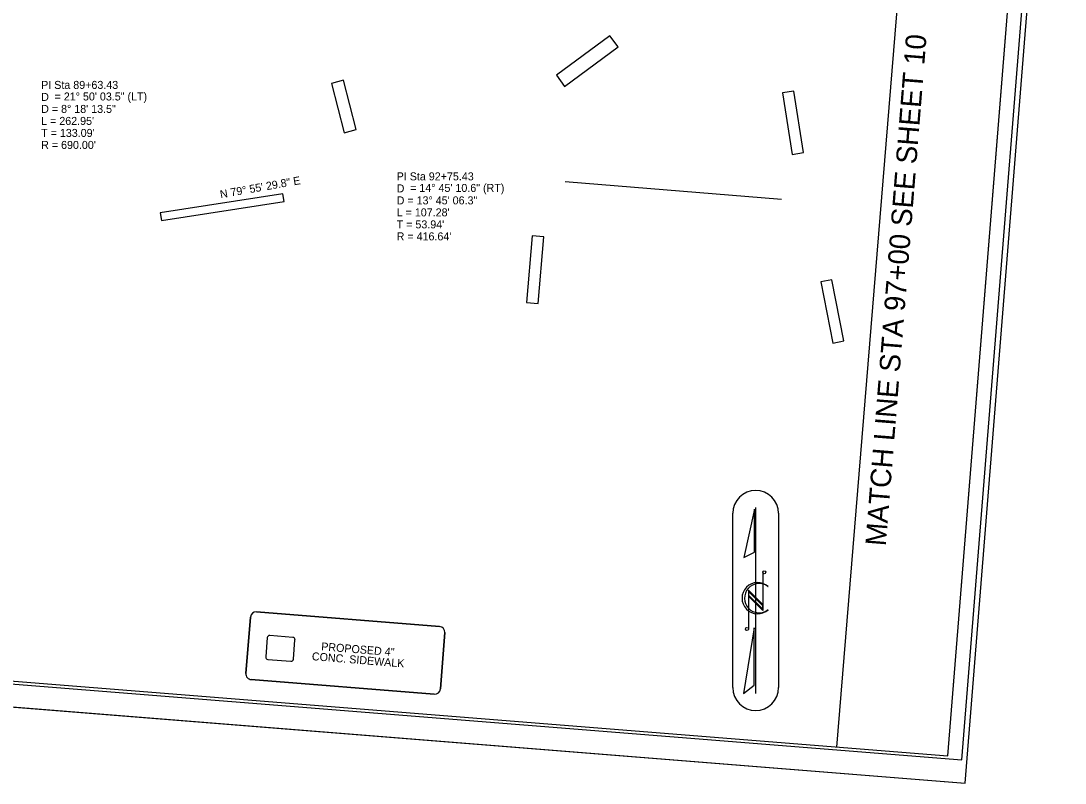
# Model space of a CAD drawing. Extents: x 928111 to 937215, y 683930 to 686530.
# Drawn here: x 935149 to 936063, y 683930 to 684597 of the extents above; entities that cross this region are included whole.
import ezdxf

# ---------------------------------------------------------------- set-up
doc = ezdxf.new("R2010")
doc.units = 0
for name, color, linetype in [('Exist Horizontal Alignment Curve and Spiral Data', 7, 'Continuous'), ('Exist Horizontal Alignment Direction Label', 7, 'Continuous'), ('Exist Horizontal Alignment Station Label', 7, 'Continuous'), ('Matchline', 7, 'Continuous'), ('Matchline Text', 7, 'Continuous'), ('Old_Level_2', 7, 'Continuous'), ('Prop DSN Text', 7, 'Continuous'), ('Prop Lane Lines', 7, 'Continuous'), ('Sheet Cutting Line CELL', 7, 'Continuous'), ('Sheet Layout Plan Border', 7, 'Continuous'), ('Sheet Plan CELL', 7, 'Continuous'), ('Sheet Plan Layout CELL', 7, 'Continuous'), ('Sheet Plot Border Inside CELL', 7, 'Continuous'), ('Sheet Plot Border Outside CELL', 7, 'Continuous')]:
    doc.layers.add(name, color=color, linetype=linetype)

msp = doc.modelspace()

# ---------------------------------------------------------------- linework, layer by layer
at = {"layer": 'Exist Horizontal Alignment Station Label'}
for p, q in [((935772.05, 684013.28), (935772.05, 684165.78)), ((935812.05, 684165.78), (935812.05, 684013.28))]:
    msp.add_line(p, q, dxfattribs=at)
for centre, start, end in [((935792.05, 684165.78), 90, 180), ((935792.05, 684165.78), 0, 90), ((935792.05, 684013.28), 180, 270), ((935792.05, 684013.28), 270, 0)]:
    msp.add_arc(centre, 20, start, end, dxfattribs=at)
at = {"layer": 'Matchline'}
msp.add_line((935863.04, 683961.34), (935931.43, 684797.06), dxfattribs=at)
at = {"layer": 'Old_Level_2'}
for p, q in [((935364.76, 684057.07), (935363.41, 684040.09)), ((935387.23, 684057.28), (935366.92, 684058.9)), ((935387.7, 684038.15), (935389.06, 684055.13)), ((935365.24, 684037.94), (935385.55, 684036.32))]:
    msp.add_line(p, q, dxfattribs=at)
for centre, start, end in [((935366.76, 684056.91), 85.42675, 175.42675), ((935387.07, 684055.29), 355.42675, 85.42675), ((935365.4, 684039.93), 175.42675, 265.42675), ((935385.71, 684038.31), 265.42675, 355.42675)]:
    msp.add_arc(centre, 2, start, end, dxfattribs=at)
at = {"layer": 'Prop DSN Text'}
for p, q in [((935350.07, 684075.01), (935346.13, 684025.71)), ((935346.13, 684025.71), (935350.07, 684075.01)), ((935515.57, 684066.79), (935355.46, 684079.6)), ((935355.46, 684079.6), (935515.57, 684066.79)), ((935516.21, 684012.1), (935520.16, 684061.41)), ((935520.16, 684061.41), (935516.21, 684012.1)), ((935350.71, 684020.33), (935510.83, 684007.52)), ((935510.83, 684007.52), (935350.71, 684020.33))]:
    msp.add_line(p, q, dxfattribs=at)
for points in [[(935624.91, 684539.21), (935671.82, 684573.75), (935664.61, 684583.55), (935617.69, 684549.01)], [(935442.67, 684501.37), (935431.47, 684544.51), (935421, 684541.79), (935432.21, 684498.66)], [(935833.97, 684481.26), (935825.5, 684535.08), (935815.37, 684533.49), (935823.84, 684479.66)], [(935272.15, 684421.83), (935379.47, 684438.5), (935378.41, 684445.34), (935271.09, 684428.67)], [(935596.62, 684408.37), (935591.66, 684350.07), (935601.84, 684349.2), (935606.81, 684407.5)], [(935848.92, 684368.17), (935859.5, 684314.68), (935869.26, 684316.61), (935858.68, 684370.1)]]:
    msp.add_lwpolyline(points, close=True, dxfattribs=at)
for centre, start, end in [((935355.06, 684074.61), 85.42675, 175.42675), ((935355.06, 684074.61), 85.42675, 175.42675), ((935515.17, 684061.81), 355.42675, 85.42675), ((935515.17, 684061.81), 355.42675, 85.42675), ((935351.11, 684025.31), 175.42675, 265.42675), ((935351.11, 684025.31), 175.42675, 265.42675), ((935511.23, 684012.5), 265.42675, 355.42675), ((935511.23, 684012.5), 265.42675, 355.42675)]:
    msp.add_arc(centre, 5, start, end, dxfattribs=at)
at = {"layer": 'Prop Lane Lines'}
msp.add_line((935625.51, 684456.02), (935814.55, 684440.55), dxfattribs=at)
at = {"layer": 'Sheet Cutting Line CELL'}
msp.add_line((934297.29, 684064), (935975.43, 683929.77), dxfattribs=at)
at = {"layer": 'Sheet Layout Plan Border'}
msp.add_line((935863.04, 683961.34), (935931.43, 684797.06), dxfattribs=at)
at = {"layer": 'Sheet Plan CELL'}
for p, q in [((935792.05, 684008.28), (935792.05, 684170.78)), ((935798.18, 684114.23), (935798.18, 684080.88)), ((935802.78, 684101.8), (935802.95, 684101.68)), ((935798.18, 684086.08), (935785.75, 684098.5)), ((935785.75, 684098.5), (935785.75, 684064.6)), ((935798.18, 684084.85), (935785.75, 684097.28)), ((935785.75, 684097.28), (935785.75, 684094.23)), ((935798.18, 684081.8), (935785.75, 684094.23)), ((935785.75, 684094.23), (935798.18, 684081.8)), ((935798.18, 684080.88), (935785.75, 684093.3)), ((935798.18, 684081.8), (935798.18, 684084.85))]:
    msp.add_line(p, q, dxfattribs=at)
for points in [[(936044.02, 685000.22), (934548.76, 685119.82), (934465.04, 684073.17), (935960.28, 683953.56)], [(935790.93, 684169.35), (935781.65, 684127.15), (935790.93, 684131.85)], [(935790.73, 684065.53), (935781.53, 684008.28), (935790.73, 684015.53)]]:
    msp.add_lwpolyline(points, close=True, dxfattribs=at)
for centre in [(935799.5, 684114.2), (935784.43, 684064.55)]:
    msp.add_circle(centre, 1.32, dxfattribs=at)
for centre, radius, start, end in [((935793.78, 684091.56), 13.65, 47.84002, 312.39406), ((935795.1, 684091.56), 12.8, 53.09504, 308.62871)]:
    msp.add_arc(centre, radius, start, end, dxfattribs=at)
at = {"layer": 'Sheet Plan Layout CELL'}
msp.add_lwpolyline([(934548.73, 685119.8), (934465.04, 684073.17), (935960.27, 683953.57), (936027.12, 684789.41), (935788.64, 684808.48), (935805.5, 685019.3)], close=True, dxfattribs=at)
at = {"layer": 'Sheet Plot Border Inside CELL'}
msp.add_lwpolyline([(934311.84, 684082.9), (935972.53, 683950.08), (936056.66, 685001.7), (934395.96, 685134.54)], close=True, dxfattribs=at)
at = {"layer": 'Sheet Plot Border Outside CELL'}
msp.add_lwpolyline([(934297.29, 684064), (935975.43, 683929.77), (936062.74, 685021.28), (934384.6, 685155.51)], close=True, dxfattribs=at)

# ---------------------------------------------------------------- texts
at = {"layer": 'Exist Horizontal Alignment Curve and Spiral Data'}
for s, p in [('PI Sta 89+63.43', (935167, 684537)), ('D', (935167, 684526.5)), ('= 21%%d 50\' 03.5" (LT)', (935178.77, 684526.89)), ('D = 8%%d 18\' 13.5"', (935167, 684516)), ("L = 262.95'", (935167, 684505.5)), ("T = 133.09'", (935167, 684495)), ("R = 690.00'", (935167, 684484.5)), ('PI Sta 92+75.43', (935478, 684457)), ('D', (935478, 684446.5)), ('= 14%%d 45\' 10.6" (RT)', (935489.77, 684446.89)), ('D = 13%%d 45\' 06.3"', (935478, 684436)), ("L = 107.28'", (935478, 684425.5)), ("T = 53.94'", (935478, 684415)), ("R = 416.64'", (935478, 684404.5))]:
    msp.add_text(s, height=7, dxfattribs=at).set_placement(p)
at = {"layer": 'Exist Horizontal Alignment Direction Label'}
msp.add_text('N 79%%d 55\' 29.8" E', height=7, rotation=10.07506, dxfattribs=at).set_placement((935324.07, 684441.27))
at = {"layer": 'Matchline Text'}
msp.add_text('MATCH LINE STA 97+00 SEE SHEET 10', height=18, rotation=85.42675, dxfattribs=at).set_placement((935905.86, 684136.72))
at = {"layer": 'Prop DSN Text'}
for s, p in [('PROPOSED 4"', (935411.81, 684045.91)), ('CONC. SIDEWALK', (935403.61, 684037.36))]:
    msp.add_text(s, height=7, rotation=355.42675, dxfattribs=at).set_placement(p)

doc.saveas('drawing.dxf')
